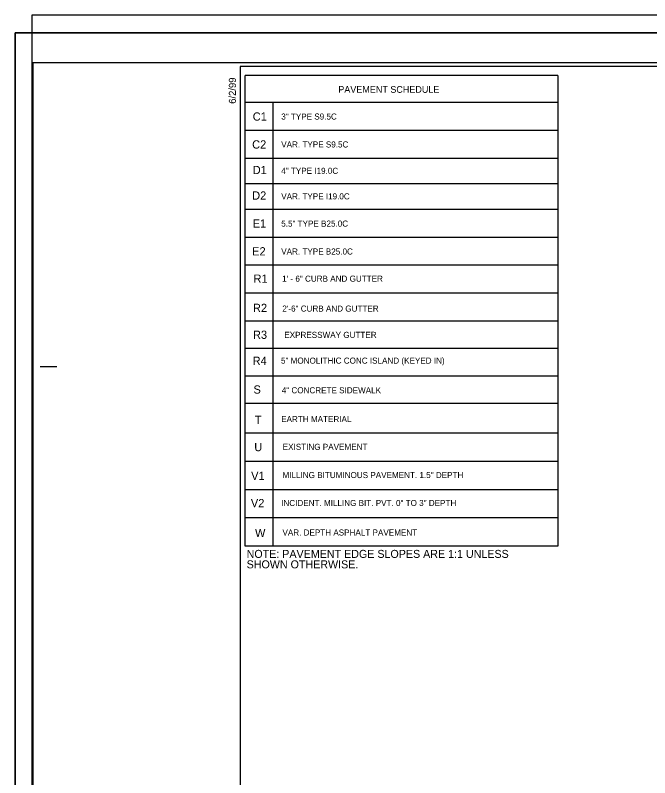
# Model space of a CAD drawing. Extents: x 2294455 to 2294795, y 719276 to 719941.
# Drawn here: x 2294454.5 to 2294548.7, y 719605.6 to 719718.8 of the extents above; entities that cross this region are included whole.
import ezdxf

# ---------------------------------------------------------------- set-up
doc = ezdxf.new("R2010")
doc.units = 0
for name, color, linetype in [('Default', 7, 'Continuous'), ('Old_Level_2', 7, 'Continuous'), ('Prop Dimension Text', 7, 'Continuous'), ('Prop Pavement Schedule Description CELL', 7, 'Continuous'), ('Sheet Plot Border Inside CELL', 7, 'Continuous'), ('Sheet Plot Border Outside CELL', 7, 'Continuous'), ('Sheet Typical CELL', 7, 'Continuous')]:
    doc.layers.add(name, color=color, linetype=linetype)

msp = doc.modelspace()

# ---------------------------------------------------------------- linework, layer by layer
at = {"layer": 'Default'}
msp.add_lwpolyline([(2294454.52, 719716.17), (2294794.52, 719716.17), (2294794.52, 719496.17), (2294454.52, 719496.17)], close=True, dxfattribs=at)
at = {"layer": 'Old_Level_2'}
msp.add_line((2294454.52, 719716.17), (2294794.52, 719716.17), dxfattribs=at)
at = {"layer": 'Prop Pavement Schedule Description CELL'}
for p, q in [((2294535.07, 719709.8), (2294488.68, 719709.8)), ((2294488.68, 719639.97), (2294488.68, 719709.8)), ((2294535.07, 719709.8), (2294535.07, 719639.97)), ((2294535.07, 719705.8), (2294488.68, 719705.8)), ((2294492.82, 719639.97), (2294492.82, 719705.8)), ((2294535.07, 719701.66), (2294488.68, 719701.66)), ((2294530.45, 719697.52), (2294488.68, 719697.52)), ((2294535.07, 719697.52), (2294488.68, 719697.52)), ((2294535.07, 719693.73), (2294488.68, 719693.73)), ((2294530.45, 719689.94), (2294488.68, 719689.94)), ((2294535.07, 719689.94), (2294488.68, 719689.94)), ((2294530.45, 719685.8), (2294488.68, 719685.8)), ((2294535.07, 719685.8), (2294488.68, 719685.8)), ((2294530.45, 719681.67), (2294488.68, 719681.67)), ((2294535.07, 719681.67), (2294488.68, 719681.67)), ((2294535.07, 719681.67), (2294488.68, 719681.67)), ((2294535.07, 719677.53), (2294488.68, 719677.53)), ((2294530.45, 719673.38), (2294488.68, 719673.38)), ((2294535.07, 719673.38), (2294488.68, 719673.38)), ((2294535.07, 719669.3), (2294488.68, 719669.3)), ((2294535.07, 719665.23), (2294488.68, 719665.23)), ((2294535.07, 719661.15), (2294488.68, 719661.15)), ((2294535.07, 719656.77), (2294488.68, 719656.77)), ((2294535.07, 719652.57), (2294488.68, 719652.57)), ((2294535.07, 719648.37), (2294488.68, 719648.37)), ((2294535.07, 719644.17), (2294488.68, 719644.17)), ((2294535.07, 719639.97), (2294488.68, 719639.97))]:
    msp.add_line(p, q, dxfattribs=at)
at = {"layer": 'Sheet Plot Border Inside CELL'}
msp.add_lwpolyline([(2294790.42, 719711.68), (2294457.12, 719711.68), (2294457.12, 719500.66), (2294790.42, 719500.66)], close=True, dxfattribs=at)
at = {"layer": 'Sheet Plot Border Outside CELL'}
for points in [[(2294793.79, 719718.76), (2294456.99, 719718.76), (2294456.99, 719498.76), (2294793.79, 719498.76)], [(2294454.52, 719496.17), (2294791.32, 719496.17), (2294791.32, 719716.17), (2294454.52, 719716.17)], [(2294794.52, 719716.17), (2294454.52, 719716.17), (2294454.52, 719496.17), (2294794.52, 719496.17)]]:
    msp.add_lwpolyline(points, close=True, dxfattribs=at)
at = {"layer": 'Sheet Typical CELL'}
msp.add_line((2294458.22, 719666.67), (2294460.72, 719666.67), dxfattribs=at)
msp.add_lwpolyline([(2294787.92, 719711.17), (2294487.92, 719711.17), (2294487.92, 719501.17), (2294787.92, 719501.17)], close=True, dxfattribs=at)

# ---------------------------------------------------------------- texts
at = {"layer": 'Prop Dimension Text'}
for s, p in [('NOTE: PAVEMENT EDGE SLOPES ARE 1:1 UNLESS', (2294488.88, 719638.25)), ('SHOWN OTHERWISE.', (2294488.88, 719636.7))]:
    msp.add_text(s, height=1.1875, dxfattribs=at).set_placement(p)
at = {"layer": 'Prop Pavement Schedule Description CELL'}
for s, height, p in [('C1', 1.225, (2294489.79, 719703.12)), ('3" TYPE S9.5C', 0.9, (2294494.02, 719703.28)), ('C2', 1.225, (2294489.7, 719698.98)), ('VAR. TYPE S9.5C', 0.9, (2294494.02, 719699.14)), ('D1', 1.225, (2294489.78, 719695.19)), ('4" TYPE I19.0C', 0.9, (2294494.02, 719695.23)), ('D2', 1.225, (2294489.7, 719691.4)), ('VAR. TYPE I19.0C', 0.9, (2294494.02, 719691.44)), ('E1', 1.225, (2294489.78, 719687.26)), ('5.5" TYPE B25.0C', 0.9, (2294494.02, 719687.4)), ('E2', 1.225, (2294489.7, 719683.12)), ('VAR. TYPE B25.0C', 0.9, (2294494.02, 719683.26)), ('R1', 1.225, (2294489.9, 719679.07)), ('1\' - 6" CURB AND GUTTER', 0.9, (2294494.15, 719679.23)), ('R2', 1.225, (2294489.82, 719674.73)), ('2\'-6" CURB AND GUTTER', 0.9, (2294494.18, 719674.79)), ('R3', 1.225, (2294489.82, 719670.74)), ('EXPRESSWAY GUTTER', 0.9, (2294494.47, 719670.89)), ('R4', 1.225, (2294489.77, 719666.88)), ('5" MONOLITHIC CONC ISLAND (KEYED IN)', 0.9, (2294493.98, 719667.07)), ('S', 1.22, (2294489.9, 719662.62)), ('4" CONCRETE SIDEWALK', 0.9, (2294494.1, 719662.67)), ('T', 1.22, (2294490.1, 719658.14)), ('EARTH MATERIAL', 0.9, (2294494.01, 719658.39)), ('U', 1.22, (2294490.02, 719654.08)), ('EXISTING PAVEMENT', 0.9, (2294494.24, 719654.28)), ('V1', 1.225, (2294489.55, 719649.81)), ('MILLING BITUMINOUS PAVEMENT. 1.5" DEPTH', 0.9, (2294494.21, 719650.09)), ('V2', 1.225, (2294489.51, 719645.77)), ('INCIDENT. MILLING BIT. PVT. 0" TO 3" DEPTH', 0.9, (2294494.01, 719645.95)), ('W', 1.22, (2294490.13, 719641.34)), ('VAR. DEPTH ASPHALT PAVEMENT', 0.9, (2294494.2, 719641.57))]:
    msp.add_text(s, height=height, dxfattribs=at).set_placement(p)
at = {"layer": 'Sheet Typical CELL'}
for s, height, rotation, p in [('6/2/99', 1.05, 90, (2294487.29, 719705.62)), ('PAVEMENT SCHEDULE', 1, 360, (2294502.49, 719707.25))]:
    msp.add_text(s, height=height, rotation=rotation, dxfattribs=at).set_placement(p)

doc.saveas('drawing.dxf')
